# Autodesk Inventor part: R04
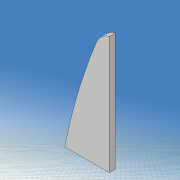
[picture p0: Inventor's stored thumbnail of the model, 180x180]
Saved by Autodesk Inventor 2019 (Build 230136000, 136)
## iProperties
Created: 2021-05
Part Number: R04
Material: 一般
Document SubType Name: Modeling
Designer: kikut
Density: 1 g/cm^3
Appearance: 既定
Mass: 0.0315871 g
Surface Area: 1.23481 cm^2
Volume: 0.0315871 cm^3
Author: kikut
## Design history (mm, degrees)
sketch "スケッチ1"
  geometry: L1 (80, 60)-(-80, 60); L2 (-80, 60)-(-80, -60); L3 (-80, -60)-(80, -60); L4 (80, -60)-(80, 60); L5 (80, 60)-(-80, -60); L6 (-80, 60)-(80, -60); 1 further point
  constraints: 12 end point, 2 midpoint, 2 parallel, 1 horizontal, 1 perpendicular
  dimensions: "d0" = 160 distance of L2.end L3.end; "d1" = 120 distance of L1.end L2.end
extrude "押し出し1" new body sketch "スケッチ1" stored distance "d2" = 0.6; taper "d3" = 0 deg
sketch "スケッチ2"
  geometry: L1 (-140, 0)-(140, 0) reference; L2 (0, -54)-(20, -30); L3 (0, 54)-(20, 30); L4 (0, -3)-(6.514, -3); L5 (6.514, -3)-(16, -6); L6 (16, -6)-(24, -3); L7 (24, -3)-(33.716, -3); L8 (0, 3)-(6.514, 3); L9 (6.514, 3)-(16, 6); L10 (16, 6)-(24, 3); L11 (24, 3)-(33.716, 3); L12 (0, -98)-(0, 98) reference; L13 (-100, -70)-(100, -70); L14 (100, -70)-(100, 70); L15 (100, 70)-(-100, 70); L16 (-100, 70)-(-100, -70); L17 (-100, -70)-(100, 70); L18 (100, -70)-(-100, 70); A1 r 60 centre (54.312, 28.5) between (0, 54) and (0, 3); A2 r 60 centre (54.312, -28.5) between (0, -3) and (0, -54); A3 r 18.111 centre (18, -12) between (20, -30) and (33.716, -3); A4 r 18.111 centre (18, 12) between (33.716, 3) and (20, 30); 1 further point
  constraints: 32 end point, 8 point on circle, 8 symmetric about line, 4 centre point, 3 horizontal, 2 collinear, 2 midpoint, 2 parallel, 1 perpendicular
  dimensions: "d5" = 60 radius of A1; "d6" = 6 distance of L8.start L4.start; "d7" = 108 distance of L3.start L2.start; "d8" = 0 horizontal distance of L3.start L8.start; "d9" = 60 distance of L3.end L2.end; "d10" = 0 horizontal distance of point (0, 0) L3.start; "d11" = 20 horizontal distance of L3.start L3.end; "d12" = 24 distance of A4.centre A3.centre; "d13" = 6 distance of L11.end L7.end; "d14" = 12 distance of L9.end L5.end; "d15" = 16 distance from line of L12 L5.end; "d16" = 24 distance from line of L6.end L12; "d17" = 200 distance of L14.end L15.end; "d18" = 140 distance of L15.end L13.start; "d30" = 18 distance from line of L12 A4.centre
extrude "押し出し2" cut sketch "スケッチ2" stored distance "d19" = 10; taper "d20" = 0 deg
sketch "スケッチ3"
  geometry: L1 (49.705, -17.97)-(33.948, -15.191); L2 (33.948, -15.191)-(34.295, -13.222); L3 (34.295, -13.222)-(50.052, -16); L4 (50.052, -16)-(49.705, -17.97); L5 (49.705, -17.97)-(34.295, -13.222); L6 (33.948, -15.191)-(50.052, -16); L7 (50.052, 16)-(34.295, 13.222); L8 (34.295, 13.222)-(33.948, 15.191); L9 (33.948, 15.191)-(49.705, 17.97); L10 (49.705, 17.97)-(50.052, 16); L11 (50.052, 16)-(33.948, 15.191); L12 (34.295, 13.222)-(49.705, 17.97); L13 (-112, 0)-(112, 0) reference; L14 (0, -84)-(0, 84) reference; 3 further points
  constraints: 24 end point, 4 midpoint, 4 parallel, 2 perpendicular, 2 symmetric about line
  dimensions: "d21" = 2 distance of L3.end L1.start; "d22" = 2 distance of L9.end L7.start; "d23" = 16 distance of L8.end L9.end; "d24" = 42 distance from line of L14 point (42, 15.596); "d26" = 10 deg angle of L7 L13; "d62" = 16 distance from line of L3.end L13
extrude "押し出し3" join sketch "スケッチ3" distance "d27" = 0.6; taper "d28" = 0 deg
fillet "フィレット1" dims "d31" = 2
fillet "フィレット2" dims "d32" = 1
sketch "スケッチ6"
  geometry: L1 (-20, 60)-(80, 60); L2 (80, 60)-(80, -60); L3 (80, -60)-(-20, -60); L4 (-20, -60)-(-20, 60); L5 (-46.168, 0)-(93.832, 0) reference; L6 (0, -84)-(0, 84) reference; L7 (-10, 40)-(0, 40); L8 (0, 40)-(0, 56); L9 (0, 56)-(-10, 56); L10 (-10, 56)-(-10, 40); 1 further point
  constraints: 16 end point, 4 parallel, 2 horizontal, 2 perpendicular, 1 other
  dimensions: "d63" = 120 distance of L3.end L1.start; "d64" = 100 distance of L1.start L1.end; "d65" = 20 distance between parallel lines of L6 L4; "d66" = 10 distance of L8.end L9.end; "d69" = 10 distance between parallel lines of L6 L10; "d73" = 16 distance of L9.end L7.start; "d74" = 40 distance between parallel lines of L7 L5
extrude "押し出し4" cut sketch "スケッチ6" stored distance "d70" = 10; taper "d71" = 0 deg
node "ソリッド1"
